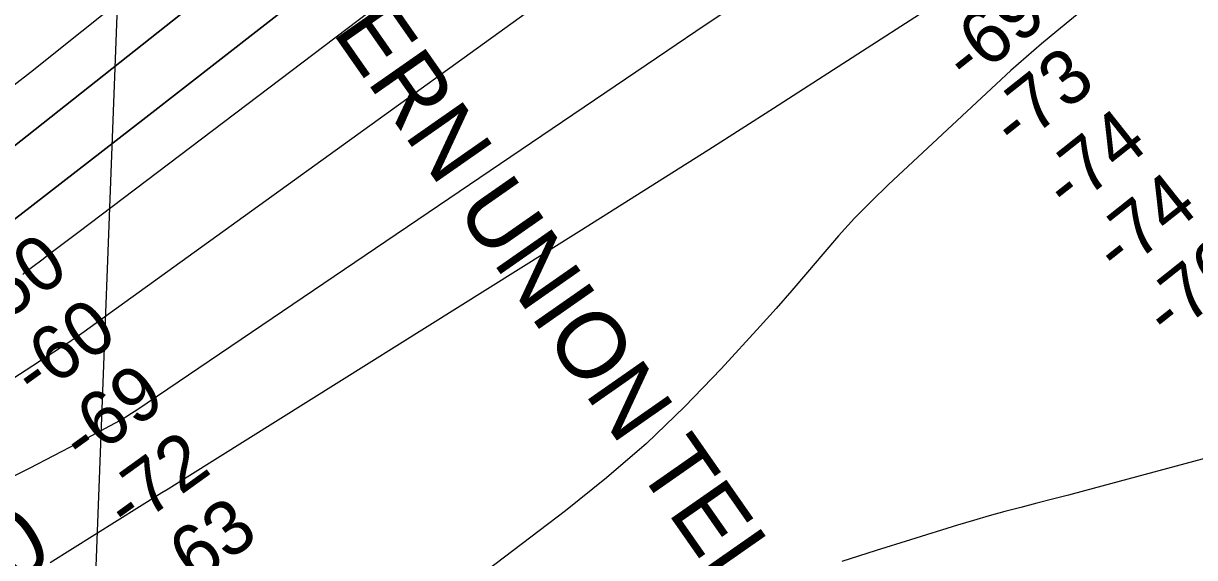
# Model space of a CAD drawing. Extents: x 3625074 to 3663148, y 511451 to 537151.
# Drawn here: x 3643476 to 3644919, y 522044 to 522702 of the extents above; entities that cross this region are included whole.
import ezdxf

# ---------------------------------------------------------------- set-up
doc = ezdxf.new("R2010")
doc.units = 0
for name, color, linetype in [('V-RIVR-RANG', 7, 'Continuous'), ('V-TOPO-DPTH', 7, 'Continuous'), ('V-TOPO-MAJR', 7, 'Continuous'), ('V-TOPO-MINR', 7, 'Continuous'), ('V-TOPO-MINR-IDEN', 7, 'Continuous'), ('V-UTIL-IDEN', 7, 'Continuous'), ('V-UTIL-LINE', 7, 'Continuous')]:
    doc.layers.add(name, color=color, linetype=linetype)

msp = doc.modelspace()

# ---------------------------------------------------------------- linework, layer by layer
at = {"layer": 'V-TOPO-DPTH'}
for points in [[(3644972.2, 523916.7), (3644897.9, 523850.8), (3644837.6, 523796.8), (3644777.6, 523742.6), (3644717.9, 523688), (3644658.5, 523633.1), (3644250.3, 523253.3), (3644247.3, 523250.5), (3644246, 523249.3), (3644245.9, 523249.2), (3644245.9, 523249.2), (3643484.8, 522641.3), (3643464.9, 522625.6), (3643444.9, 522609.9), (3643424.8, 522594.4), (3643404.7, 522579), (3643370.1, 522552.8), (3643367.1, 522550.6), (3643364.2, 522548.4), (3643361.2, 522546.2), (3643358.3, 522544.1), (3642720.8, 522086), (3642676.3, 522054.1), (3642631.9, 522022.2)], [(3644972.2, 523916.7), (3644897.9, 523850.8), (3644837.6, 523796.8), (3644777.6, 523742.6), (3644717.9, 523688), (3644658.5, 523633.1), (3644250.3, 523253.3), (3644247.3, 523250.5), (3644246, 523249.3), (3644245.9, 523249.2), (3644245.9, 523249.2), (3643484.8, 522641.3), (3643464.9, 522625.6), (3643444.9, 522609.9), (3643424.8, 522594.4), (3643404.7, 522579), (3643370.1, 522552.8), (3643367.1, 522550.6), (3643364.2, 522548.4), (3643361.2, 522546.2), (3643358.3, 522544.1), (3642720.8, 522086), (3642676.3, 522054.1), (3642631.9, 522022.2)], [(3643453.1, 522541.3), (3643811.3, 522825.3), (3643889.8, 522887.9), (3643968, 522950.9), (3644045.8, 523014.4), (3644123.4, 523078.2), (3644236.7, 523172), (3644257.3, 523189.3), (3644277.8, 523206.6), (3644298.2, 523224.2), (3644318.5, 523241.8), (3644463.7, 523369.4), (3644556.3, 523451.2), (3644648.5, 523533.4), (3644740.2, 523616.2), (3644831.5, 523699.4), (3645042.5, 523892.8)], [(3643453.1, 522541.3), (3643811.3, 522825.3), (3643889.8, 522887.9), (3643968, 522950.9), (3644045.8, 523014.4), (3644123.4, 523078.2), (3644236.7, 523172), (3644257.3, 523189.3), (3644277.8, 523206.6), (3644298.2, 523224.2), (3644318.5, 523241.8), (3644463.7, 523369.4), (3644556.3, 523451.2), (3644648.5, 523533.4), (3644740.2, 523616.2), (3644831.5, 523699.4), (3645042.5, 523892.8)], [(3644952.9, 523717.4), (3644697.3, 523474.3), (3644636.9, 523417.6), (3644575.9, 523361.5), (3644514.1, 523306.3), (3644451.7, 523251.8), (3644351, 523164.9), (3644338.5, 523154.3), (3644326, 523143.7), (3644313.3, 523133.3), (3644300.6, 523122.9), (3643996.3, 522877.7), (3643904.5, 522804), (3643812.4, 522730.8), (3643719.8, 522658.1), (3643627, 522585.7), (3643471.7, 522465.3), (3643456.3, 522453.4), (3643440.9, 522441.5), (3643425.5, 522429.7), (3643410.1, 522417.8), (3642843.4, 521983.4)], [(3642843.4, 521983.4), (3643410.1, 522417.8), (3643425.5, 522429.7), (3643440.9, 522441.5), (3643456.3, 522453.4), (3643471.7, 522465.3), (3643627, 522585.7), (3643719.8, 522658.1), (3643812.4, 522730.8), (3643904.5, 522804), (3643996.3, 522877.7), (3644300.6, 523122.9), (3644313.3, 523133.3), (3644326, 523143.7), (3644338.5, 523154.3), (3644351, 523164.9), (3644451.7, 523251.8), (3644514.1, 523306.3), (3644575.9, 523361.5), (3644636.9, 523417.6), (3644697.3, 523474.3), (3644952.9, 523717.4)]]:
    msp.add_lwpolyline(points, dxfattribs=at)
at = {"layer": 'V-TOPO-MAJR'}
msp.add_lwpolyline([(3644973.5, 523509.3), (3644892.4, 523455.4), (3644812.1, 523400.4), (3644733, 523343.6), (3644654.7, 523285.7), (3644444.8, 523126.8), (3644411.9, 523102), (3644379.1, 523077.2), (3644346.3, 523052.3), (3644313.5, 523027.5), (3643545, 522444.9), (3643533.5, 522436.2), (3643522, 522427.5), (3643510.5, 522418.8), (3643499, 522410.1), (3643476.8, 522393.5), (3643475.4, 522392.4)], dxfattribs=at)
at = {"layer": 'V-TOPO-MINR'}
for points in [[(3644972.2, 523916.7), (3644897.9, 523850.8), (3644837.6, 523796.8), (3644777.6, 523742.6), (3644717.9, 523688), (3644658.5, 523633.1), (3644250.3, 523253.3), (3644247.3, 523250.5), (3644246, 523249.3), (3644245.9, 523249.2), (3644245.9, 523249.2), (3643484.8, 522641.3), (3643464.9, 522625.6), (3643444.9, 522609.9), (3643424.8, 522594.4), (3643404.7, 522579), (3643370.1, 522552.8), (3643367.1, 522550.6), (3643364.2, 522548.4), (3643361.2, 522546.2), (3643358.3, 522544.1), (3642720.8, 522086), (3642676.3, 522054.1), (3642631.9, 522022.2)], [(3645042.5, 523892.8), (3644831.5, 523699.4), (3644740.2, 523616.2), (3644648.5, 523533.4), (3644556.3, 523451.2), (3644463.7, 523369.4), (3644318.5, 523241.8), (3644298.2, 523224.2), (3644277.8, 523206.6), (3644257.3, 523189.3), (3644236.7, 523172), (3644123.4, 523078.2), (3644045.8, 523014.4), (3643968, 522950.9), (3643889.8, 522887.9), (3643811.3, 522825.3), (3643453.1, 522541.3)], [(3644952.9, 523717.4), (3644697.3, 523474.3), (3644636.9, 523417.6), (3644575.9, 523361.5), (3644514.1, 523306.3), (3644451.7, 523251.8), (3644351, 523164.9), (3644338.5, 523154.3), (3644326, 523143.7), (3644313.3, 523133.3), (3644300.6, 523122.9), (3643996.3, 522877.7), (3643904.5, 522804), (3643812.4, 522730.8), (3643719.8, 522658.1), (3643627, 522585.7), (3643471.7, 522465.3), (3643456.3, 522453.4), (3643440.9, 522441.5), (3643425.5, 522429.7), (3643410.1, 522417.8), (3642843.4, 521983.4)], [(3644973.1, 523329.9), (3644871, 523258.8), (3644768.6, 523188.2), (3644666, 523117.9), (3644505, 523008.4), (3644482.7, 522993), (3644460.5, 522977.6), (3644438.4, 522962), (3644416.4, 522946.3), (3643540.6, 522314.4), (3643538.7, 522313.1), (3643534.9, 522310.4), (3643531, 522307.9), (3643530.2, 522307.4), (3642618.3, 521714.6)], [(3643509.2, 522037.6), (3643646.7, 522123.6), (3643654.4, 522128.4), (3643662.2, 522133.2), (3643669.9, 522138.1), (3643677.7, 522143), (3644160.3, 522445.2), (3644240.5, 522495.7), (3644320.5, 522546.4), (3644400.3, 522597.4), (3644480, 522648.6), (3644610.1, 522732.8), (3644624.5, 522742.3), (3644638.6, 522752.1), (3644652.5, 522762.3), (3644666.2, 522772.7), (3645137, 523142.4)], [(3645100.8, 522980.7), (3644749.3, 522692.2), (3644730.2, 522676.3), (3644711.3, 522660), (3644692.7, 522643.5), (3644674.4, 522626.7), (3644541.8, 522503.1), (3644520.7, 522482.6), (3644500.1, 522461.6), (3644480.3, 522439.8), (3644461.1, 522417.5), (3644442.1, 522395), (3644422.9, 522372.6), (3644403.4, 522350.6), (3644383.7, 522328.7), (3644335.6, 522276), (3644290.5, 522229.2), (3644243.7, 522184.1), (3644194.6, 522141.7), (3644143.9, 522101), (3643874.2, 521896.4)], [(3644363.5, 522731.7), (3644316.1, 522699.6), (3644268.7, 522667.4), (3643616, 522225.3), (3643609.3, 522220.9), (3643602.4, 522216.6), (3643595.4, 522212.5), (3643588.4, 522208.6), (3643543, 522184.4), (3643513.1, 522168.7), (3643483.1, 522153.3), (3643452.9, 522138.2)], [(3644960.3, 522173.4), (3644783.1, 522125.8), (3644763.5, 522120.6), (3644744, 522115.5), (3644724.4, 522110.4), (3644704.8, 522105.4), (3644685.3, 522100.3), (3644665.8, 522095), (3644646.4, 522089.3), (3644627, 522083.5), (3644569.1, 522065.4), (3644526.8, 522052.2), (3644484.5, 522038.9)]]:
    msp.add_lwpolyline(points, dxfattribs=at)
at = {"layer": 'V-UTIL-LINE'}
msp.add_line((3643607.2, 523139.9), (3643488.1, 519983.4), dxfattribs=at)

# ---------------------------------------------------------------- texts
at = {"layer": 'V-RIVR-RANG'}
for s, rotation, p in [('-69', 38.4385, (3644639.4, 522625.2)), ('-73', 38.4385, (3644698.3, 522544.3)), ('-74', 38.4385, (3644762.9, 522467.9)), ('-74', 38.4385, (3644824.9, 522389.5)), ('-50', 35.8126, (3643430.3, 522317.1)), ('-76', 38.4385, (3644886.7, 522310.8)), ('-60', 35.8126, (3643490.3, 522237.1)), ('-69', 35.8126, (3643549.5, 522156.5)), ('-72', 35.8126, (3643605, 522073.2)), ('-63', 35.8126, (3643663.3, 521992))]:
    msp.add_text(s, height=67, rotation=rotation, dxfattribs=at).set_placement(p)
at = {"layer": 'V-TOPO-MINR-IDEN'}
msp.add_text('-70', height=83, rotation=31.7427, dxfattribs=at).set_placement((3643379.3, 521957.2))
at = {"layer": 'V-UTIL-IDEN'}
for s, rotation, p in [('WESTERN UNION TEL. CO.', 304.9242, (3643672.3, 522953.8)), ('LA. POWER & LT.', 316.7851, (3644796, 522951.5))]:
    msp.add_text(s, height=83, rotation=rotation, dxfattribs=at).set_placement(p)

doc.saveas('drawing.dxf')
